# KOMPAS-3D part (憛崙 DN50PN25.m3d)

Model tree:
1. Объединить компоненты:1  (labels: СЕНС DN50PN25)

Referenced files in D:\Савин\!СЕНСОР\3D для заказчика\!Новый перечень\СЕНС\1. СЕНС\DN50\: СЕНС DN50PN25.a3d
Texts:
  СЕНС DN50PN25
